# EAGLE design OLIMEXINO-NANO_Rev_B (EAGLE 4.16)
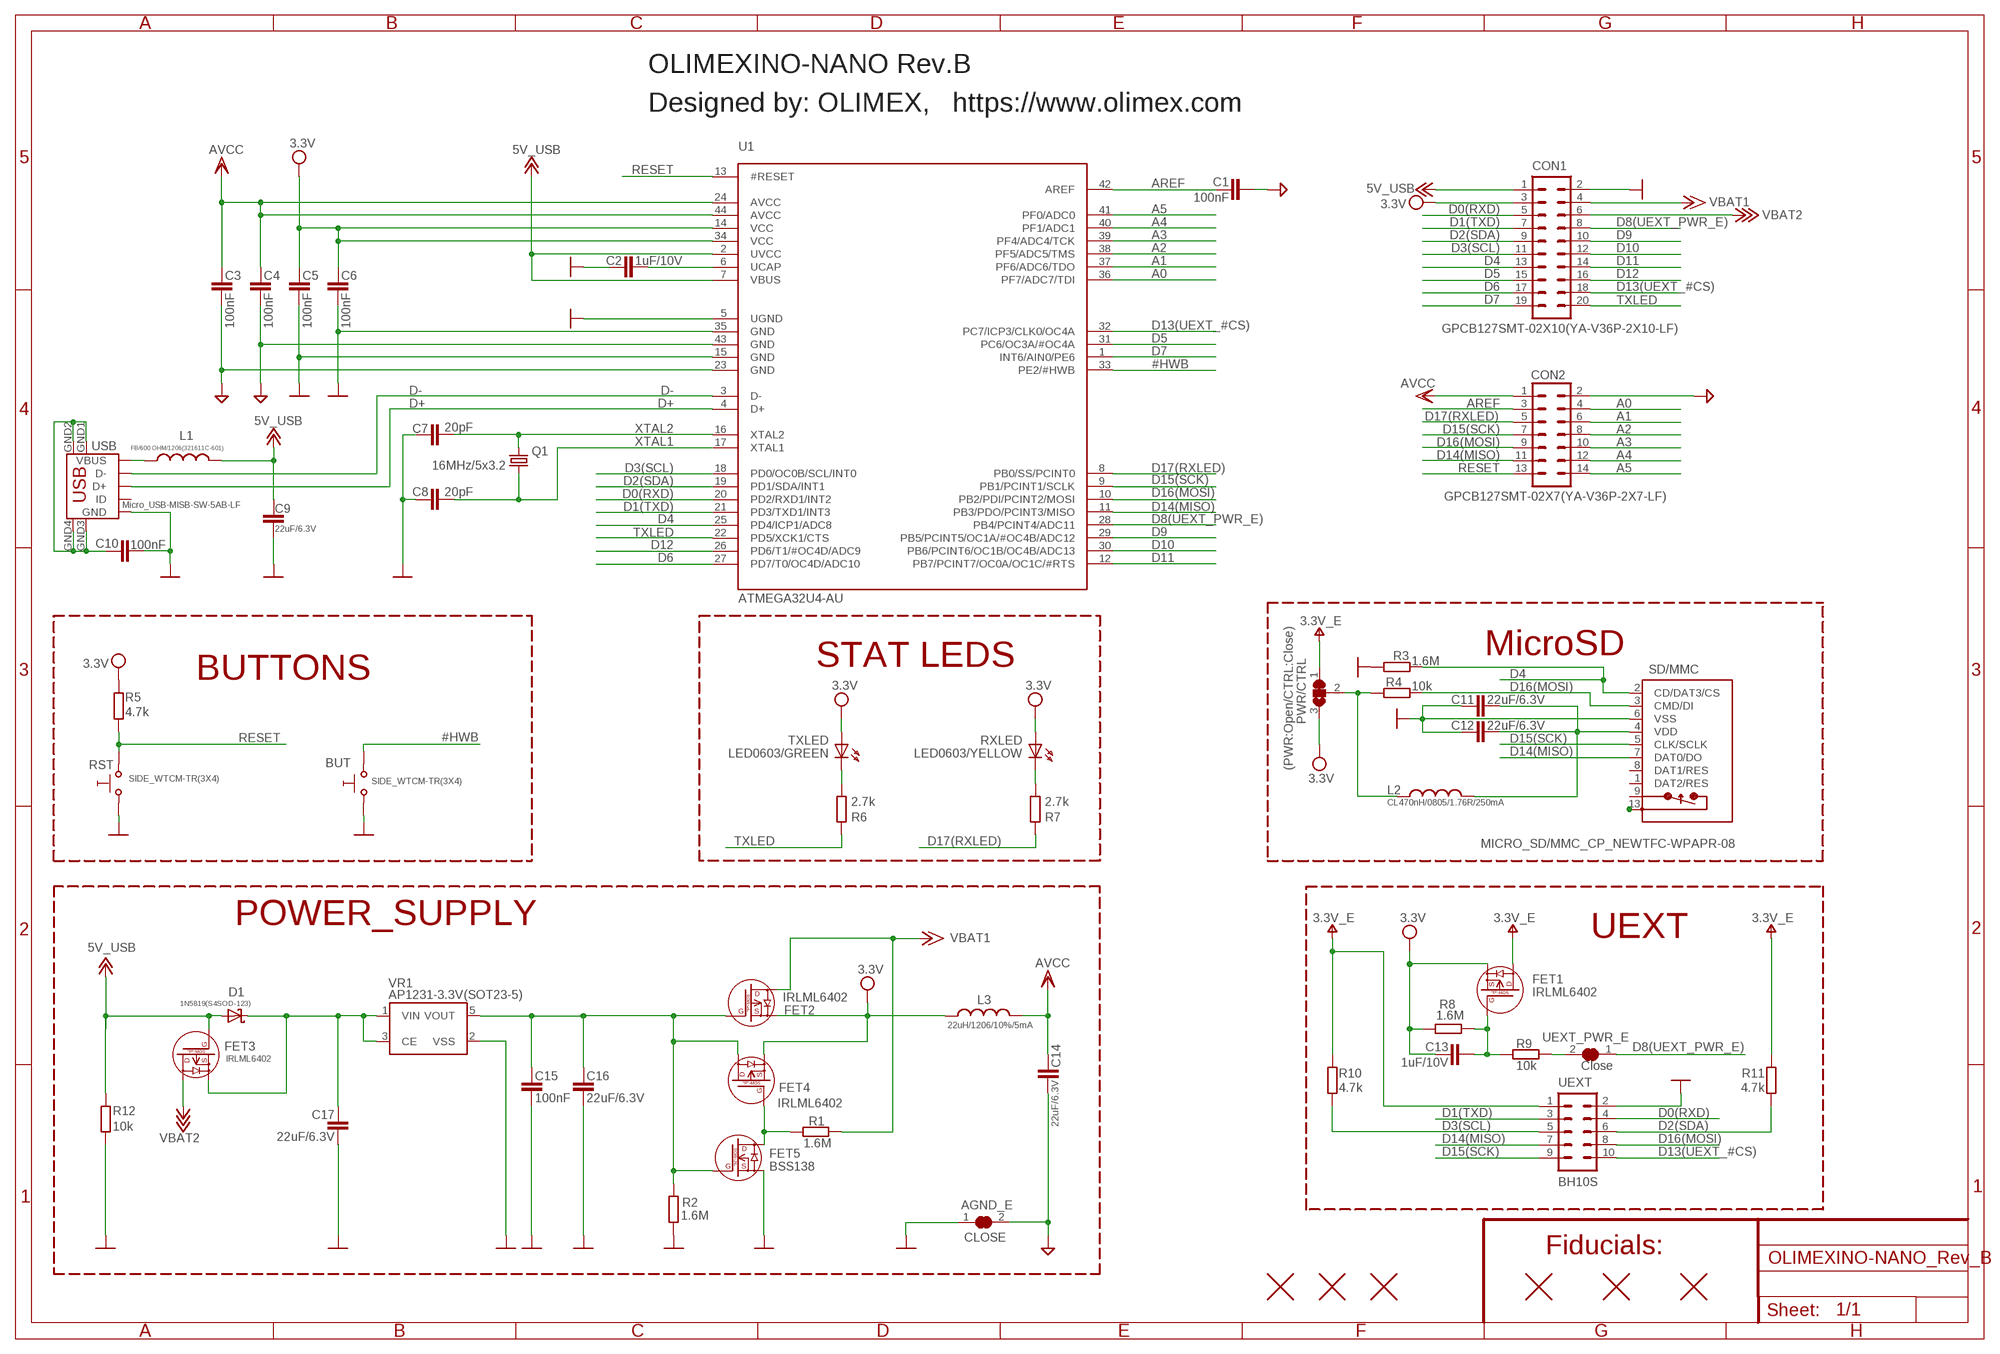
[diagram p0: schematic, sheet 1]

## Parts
AGND_E  CLOSE  SJSJ_1_SMALLER_CLOSE  [SJ_1_SMALLER_CLOSE]
BUT  SIDE_WTCM-TR(3X4)  SW-TAKTSIDE_WTCM-TR(3X4)  [SW_TAKT3X4]
C1  100nF  C-EUC0603_DWS  [C0603_DWS]
C2  1uF/10V  C-EUC0603_DWS  [C0603_DWS]
C3  100nF  C-EUC0402_TI  [C0402_TI]
C4  100nF  C-EUC0603_DWS  [C0603_DWS]
C5  100nF  C-EUC0603_DWS  [C0603_DWS]
C6  100nF  C-EUC0603_DWS  [C0603_DWS]
C7  20pF  C-EUC0603_DWS  [C0603_DWS]
C8  20pF  C-EUC0603_DWS  [C0603_DWS]
C9  22uF/6.3V  C-EUC0603_DWS  [C0603_DWS]
C10  100nF  C-EUC0603_DWS  [C0603_DWS]
C11  22uF/6.3V  C-EUC0603_DWS  [C0603_DWS]
C12  22uF/6.3V  C-EUC0603_DWS  [C0603_DWS]
C13  1uF/10V  C-EUC0603_DWS  [C0603_DWS]
C14  22uF/6.3V  C-EUC0603_DWS  [C0603_DWS]
C15  100nF  C-EUC0603_DWS  [C0603_DWS]
C16  22uF/6.3V  C-EUC0603_DWS  [C0603_DWS]
C17  22uF/6.3V  C-EUC0603_DWS  [C0603_DWS]
CON1  GPCB127SMT-02X10(YA-V36P-2X10-LF)  ML20YA-V36P-2X10-LF  [YA-V36P-2X10-LF]
CON2  GPCB127SMT-02X7(YA-V36P-2X7-LF)  ML14YA-V36P-2X7-LF  [YA-V36P-2X7-LF]
D1  1N5819(S4SOD-123)  SCHOTKKY7.62SS-1N5819(S4SOD-123)  [SOD-123]
FET1  IRLML6402  P-MOS+DIODIRLML6402  [SOT23]
FET2  IRLML6402  P-MOS+DIODIRLML6402  [SOT23]
FET3  IRLML6402  P-MOS+DIODIRLML6402  [SOT23]
FET4  IRLML6402  P-MOS+DIODIRLML6402  [SOT23]
FET5  BSS138  N-MOS+DIODBSS138(SOT23-3)  [SOT23]
FID1  FIDUCIAL  [FIDUCIAL-1X3]
FID2  FIDUCIAL  [FIDUCIAL-1X3]
FID3  FIDUCIAL  [FIDUCIAL-1X3]
FID4  FIDUCIAL  [FIDUCIAL-1X3]
FID5  FIDUCIAL  [FIDUCIAL-1X3]
FID6  FIDUCIAL  [FIDUCIAL-1X3]
L1  FB/600 OHM/1206(321611C-601)  L-USL3216C  [L3216C]
L2  CL470nH/0805/1.76R/250mA  L-USL0805_5MIL_DWS  [L0805_5MIL_DWS]
L3  22uH/1206/10%/5mA  L-USL3216C  [L3216C]
PWR/CTRL  (PWR:Open/CTRL:Close)  SJ2W6  [SJ_2_SMALL_12_TIED]
Q1  16MHz/5x3.2  HC49/S_E4SB25.000F20E15  [HCX-4S]
R1  1.6M  R-EU_R0603_5MIL_DWS  [R0603_5MIL_DWS]
R2  1.6M  R-EU_R0603_5MIL_DWS  [R0603_5MIL_DWS]
R3  1.6M  R-EU_R0603_5MIL_DWS  [R0603_5MIL_DWS]
R4  10k  R-EU_R0603_5MIL_DWS  [R0603_5MIL_DWS]
R5  4.7k  R-EU_R0603_5MIL_DWS  [R0603_5MIL_DWS]
R6  2.7k  R-EU_R0603_5MIL_DWS  [R0603_5MIL_DWS]
R7  2.7k  R-EU_R0603_5MIL_DWS  [R0603_5MIL_DWS]
R8  1.6M  R-EU_R0603_5MIL_DWS  [R0603_5MIL_DWS]
R9  10k  R-EU_R0603_5MIL_DWS  [R0603_5MIL_DWS]
R10  4.7k  R-EU_R0603_5MIL_DWS  [R0603_5MIL_DWS]
R11  4.7k  R-EU_R0603_5MIL_DWS  [R0603_5MIL_DWS]
R12  10k  R-EU_R0603_5MIL_DWS  [R0603_5MIL_DWS]
RST  SIDE_WTCM-TR(3X4)  SW-TAKTSIDE_WTCM-TR(3X4)  [SW_TAKT3X4]
RXLED  LED0603/YELLOW  LED0603DWS  [LED-0603]
SD/MMC  MICRO_SD/MMC_CP_NEWTFC-WPAPR-08  [TFC-WPAPR-08]
TXLED  LED0603/GREEN  LED0603DWS  [LED-0603]
U1  ATMEGA32U4-AU  ATMEGA32U4U  [TQFP44]
UEXT  BH10S  ML10SMD  [ML10_PADS]
UEXT_PWR_E  Close  SJSJ_1_SMALLER_CLOSE  [SJ_1_SMALLER_CLOSE]
USB  Micro_USB-MISB-SW-5AB-LF  MINI_USB9MISB-SW-5AB-LF  [MISB-SW-5AB-LF]
VR1  AP1231-3.3V(SOT23-5)  AP1231-33  [SOT-23-5]

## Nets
#HWB: BUT.1_1 U1.33(PE2/#HWB)
+12V: C9.1 CON1.1 D1.A FET3.1(G) L1.2 R12.1 U1.2(UVCC) U1.7(VBUS) ; supply symbol labelled 5V_USB
+15V: CON1.4 FET2.3(D) R1.1 ; supply symbol labelled VBAT1
+18V: CON1.6 FET3.3(D) ; supply symbol labelled VBAT2
A0: CON2.4 U1.36(PF7/ADC7/TDI)
A1: CON2.6 U1.37(PF6/ADC6/TDO)
A2: CON2.8 U1.38(PF5/ADC5/TMS)
A3: CON2.10 U1.39(PF4/ADC4/TCK)
A4: CON2.12 U1.40(PF1/ADC1)
A5: CON2.14 U1.41(PF0/ADC0)
AGND: AGND_E.2 C1.2 C3.2 C4.2 C14.2 CON2.2 U1.23(GND) U1.43(GND)
AREF: C1.1 CON2.3 U1.42(AREF)
D0(RXD): CON1.5 U1.20(PD2/RXD1/INT2) UEXT.4
D1(TXD): CON1.7 U1.21(PD3/TXD1/INT3) UEXT.3
D2(SDA): CON1.9 R11.1 U1.19(PD1/SDA/INT1) UEXT.6
D3(SCL): CON1.11 R10.1 U1.18(PD0/OC0B/SCL/INT0) UEXT.5
D4: CON1.13 R3.1 SD/MMC.2(CD/DAT3/CS) U1.25(PD4/ICP1/ADC8)
D5: CON1.15 U1.31(PC6/OC3A/#OC4A)
D6: CON1.17 U1.27(PD7/T0/OC4D/ADC10)
D7: CON1.19 U1.1(INT6/AIN0/PE6)
D8(UEXT_PWR_E): CON1.8 U1.28(PB4/PCINT4/ADC11) UEXT_PWR_E.1
D9: CON1.10 U1.29(PB5/PCINT5/OC1A/#OC4B/ADC12)
D10: CON1.12 U1.30(PB6/PCINT6/OC1B/OC4B/ADC13)
D11: CON1.14 U1.12(PB7/PCINT7/OC0A/OC1C/#RTS)
D12: CON1.16 U1.26(PD6/T1/#OC4D/ADC9)
D13(UEXT_#CS): CON1.18 U1.32(PC7/ICP3/CLK0/OC4A) UEXT.10
D14(MISO): CON2.11 SD/MMC.7(DAT0/DO) U1.11(PB3/PDO/PCINT3/MISO) UEXT.7
D15(SCK): CON2.7 SD/MMC.5(CLK/SCLK) U1.9(PB1/PCINT1/SCLK) UEXT.9
D16(MOSI): CON2.9 R4.1 SD/MMC.3(CMD/DI) U1.10(PB2/PDI/PCINT2/MOSI) UEXT.8
D17(RXLED): CON2.5 R7.2 U1.8(PB0/SS/PCINT0)
D+: U1.4(D+) USB.D+
D-: U1.3(D-) USB.D-
GND [pwr]: AGND_E.1 BUT.2_1 C2.1 C5.2 C6.2 C7.1 C8.1 C9.2 C10.2 C11.1 C12.1 C15.2 C16.2 C17.2 CON1.2 FET5.2(S) R2.2 R3.2 R12.2 RST.1_1 SD/MMC.6(VSS) U1.5(UGND) U1.15(GND) U1.35(GND) UEXT.2 USB.GND VR1.2(VSS)
N$2: FET4.1(G) FET5.3(D) R1.2
N$5: R6.1 TXLED.C
N$6: R9.2 UEXT_PWR_E.2
N$7: SD/MMC.10(PACK1) SD/MMC.11(PACK2) SD/MMC.12(PACK3) SD/MMC.13(PACK4)
N$8: C15.1 C16.1 FET2.1(G) FET4.3(D) FET5.1(G) R2.1 VR1.5(VOUT)
N$18: L2.1 PWR/CTRL.2 R4.2
N$19: C13.2 FET1.1(G) R8.2 R9.1
N$23: R7.1 RXLED.C
N$118: C10.1 USB.GND1 USB.GND2 USB.GND3 USB.GND4
RESET: CON2.13 R5.2 RST.2_1 U1.13(#RESET)
SD_VCC: C11.2 C12.2 L2.2 SD/MMC.4(VDD)
TXLED: CON1.20 R6.2 U1.22(PD5/XCK1/CTS)
UCAP: C2.2 U1.6(UCAP)
V+: FET1.3(D) PWR/CTRL.1 R10.2 R11.2 UEXT.1 ; supply symbol labelled 3.3V_E
VBUS: L1.1 USB.VBUS
VCC: C5.1 C6.1 C13.1 CON1.3 FET1.2(S) FET2.2(S) FET4.2(S) L3.1 PWR/CTRL.3 R5.1 R8.1 RXLED.A TXLED.A U1.14(VCC) U1.34(VCC) ; supply symbol labelled 3.3V
VDD: C3.1 C4.1 C14.1 CON2.1 L3.2 U1.24(AVCC) U1.44(AVCC) ; supply symbol labelled AVCC
VIN: C17.1 D1.C FET3.2(S) VR1.1(VIN) VR1.3(CE)
XTAL1: C8.2 Q1.2 U1.17(XTAL1)
XTAL2: C7.2 Q1.1 U1.16(XTAL2)
Unconnected: SD/MMC.1(DAT2/RES) SD/MMC.8(DAT1/RES) SD/MMC.9(CP_E) USB.ID

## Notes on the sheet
- OLIMEXINO-NANO Rev.B
- Designed by: OLIMEX,   https://www.olimex.com
- MicroSD
- STAT LEDS
- BUTTONS
- POWER_SUPPLY
- UEXT
- Fiducials:

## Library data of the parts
AGND_E UEXT_PWR_E = jumper:SJ: SMD solder JUMPER
BUT RST = gogo:SW-TAKT
C1-C17 = rcl:C-EU: CAPACITOR, European symbol
CON1 = con-harting-ml:ML20: HARTING
CON2 = con-harting-ml:ML14: HARTING
D1 = gogo:SCHOTKKY7.62SS
FET1-FET4 = Penko:P-MOS+DIOD
FET5 = Penko:N-MOS+DIOD
FID1-FID6 = SparkFunEagle-6-6-07:FIDUCIAL: Fiducial Alignment Points
L1-L3 = rcl:L-US: INDUCTOR, American symbol
PWR/CTRL = jumper:SJ2W: SMD solder JUMPER
Q1 = crystal:HC49/S: CRYSTAL
R1-R12 = rcl:R-EU_: RESISTOR, European symbol
RXLED TXLED = DOUBLE-SIDE:LED
SD/MMC = OLIMEX_CONNECTORS:MICRO_SD/MMC_CP_NEW
U1 = OLIMEX_IC:ATMEGA32U4: 8-bit Microcontroller with 16/32K Bytes of ISP Flash and USB Controller
UEXT = con-harting-ml:ML10: HARTING
USB = OLIMEX_CONNECTORS:MINI_USB9
VR1 = OLIMEX_DISCRET:AP1231

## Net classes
1 pwr: width 0.25 mm

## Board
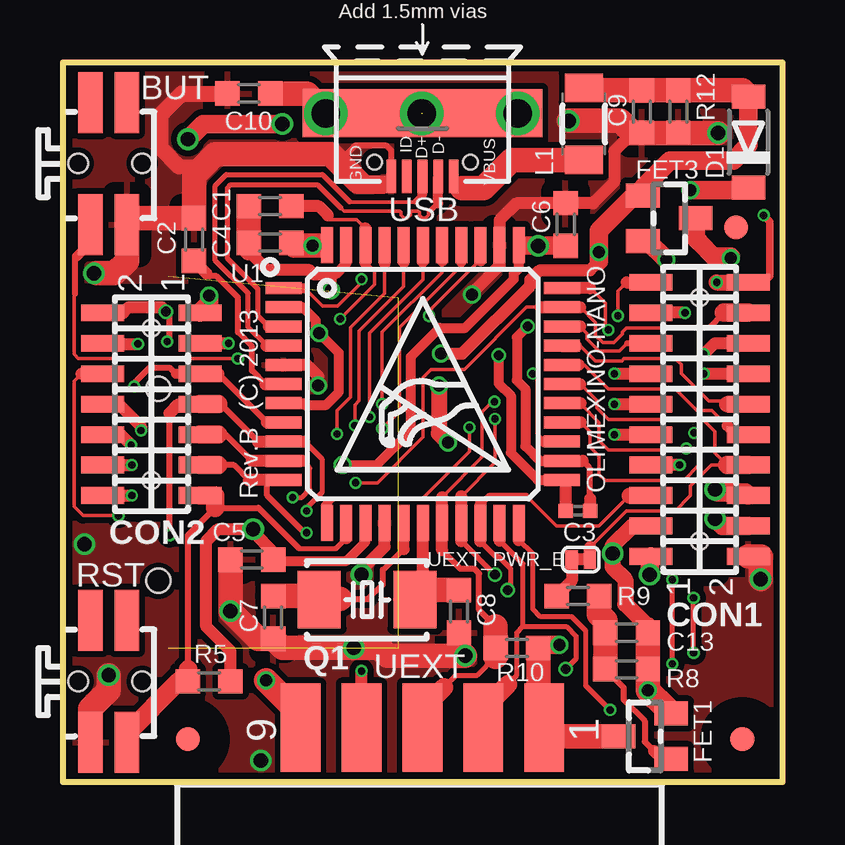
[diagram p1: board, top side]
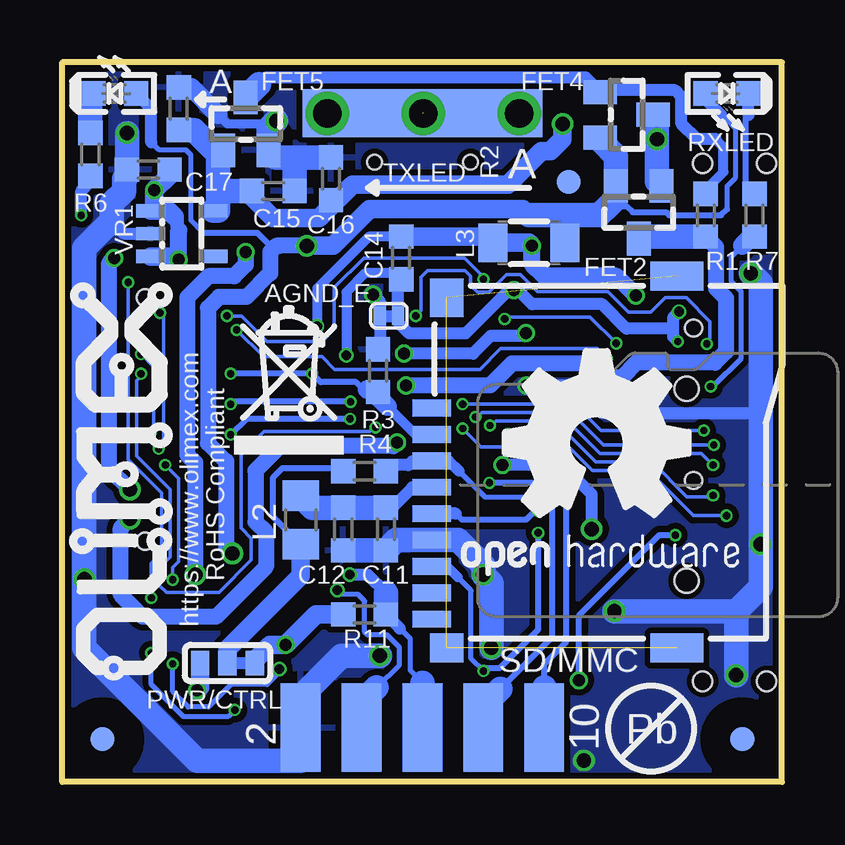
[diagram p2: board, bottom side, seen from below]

Size 30 x 30 mm. Coordinates in mm from the lower left corner, seen from the top.
Outline: 0,0 30,0 30,30 0,30 0,0
Copper layers (1+16): Top 0.035mm / dielectric 1.5mm / Bottom 0.035mm
Design rules "default": minimum track width 6mil, minimum drill 0.4mm, track to track 0.2mm, track to pad 0.2mm, pad to pad 0.2mm, via to via 0.2mm, smd to smd 1mil, copper to edge 10mil, drill to drill 8mil, minimum pad ring 8mil, minimum via ring 4mil, stop-mask expansion 4mil, vias tented up to drill 25mil, thermal gap 20mil
tRestrict: 4 lines

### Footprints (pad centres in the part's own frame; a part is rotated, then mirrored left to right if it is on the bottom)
SJ_1_SMALLER_CLOSE = smd 0.508 x 0.762: 1 -0.381,0; 2 0.381,0
SW_TAKT3X4 = smd 2.54 x 1.016: 1_1 -2.54,0.762; 1_2 2.54,0.762; 2_1 -2.54,-0.762; 2_2 2.54,-0.762 | hole 0.8: 0,-1.397; 0,1.27
C0603_DWS = smd 1.016 x 1.016: 1 -0.889,0; 2 0.889,0
C0402_TI = smd 0.61 x 0.584: 1 -0.508,0; 2 0.508,0
YA-V36P-2X10-LF = smd 0.7 x 1.8: 1 -5.715,2.032; 2 -5.715,-2.032; 3 -4.445,2.032; 4 -4.445,-2.032; 5 -3.175,2.032; 6 -3.175,-2.032; 7 -1.905,2.032; 8 -1.905,-2.032; 9 -0.635,2.032; 10 -0.635,-2.032; 11 0.635,2.032; 12 0.635,-2.032; 13 1.905,2.032; 14 1.905,-2.032; 15 3.175,2.032; 16 3.175,-2.032; 17 4.445,2.032; 18 4.445,-2.032; 19 5.715,2.032; 20 5.715,-2.032 | hole 0.7: -5.08,0; 5.08,0
YA-V36P-2X7-LF = smd 0.7 x 1.8: 1 -3.81,2.032; 2 -3.81,-2.032; 3 -2.54,2.032; 4 -2.54,-2.032; 5 -1.27,2.032; 6 -1.27,-2.032; 7 0,2.032; 8 0,-2.032; 9 1.27,2.032; 10 1.27,-2.032; 11 2.54,2.032; 12 2.54,-2.032; 13 3.81,2.032; 14 3.81,-2.032 | hole 0.7: -3.175,0; 3.175,0
SOD-123 = smd 1 x 1.4: A 1.9,0; C -1.9,0
SOT23 = smd 1 x 1.4: 1 -0.95,-1.1; 2 0.95,-1.1; 3 0,1.1
FIDUCIAL-1X3 = smd 1 x 1: 1 0,0
L3216C = smd 1.2 x 1.6: 1 -1.5,0; 2 1.5,0
L0805_5MIL_DWS = smd 1.27 x 1.524: 1 -1.016,0; 2 1.016,0
SJ_2_SMALL_12_TIED = smd 0.762 x 1.016: 1 -1.143,0; 2 0,0; 3 1.143,0
HCX-4S = smd 1.8 x 2.4: 1 -2,0; 2 2,0
R0603_5MIL_DWS = smd 1.016 x 1.016: 1 -0.889,0; 2 0.889,0
LED-0603 = smd 1.016 x 1.016: A 0.889,0; C -0.889,0
TFC-WPAPR-08 = smd 0.7 x 1.6: 1 -3.2,-0.125; 2 -2.1,-0.125; 3 -1,-0.125; 4 0.1,-0.125; 5 1.2,-0.125; 6 2.3,-0.125; 7 3.4,-0.125; 8 4.5,-0.125; 9 5.6,-0.125 | smd 1.2 x 1.4: 10 6.8,0.5 | smd 1.6 x 1.4: 11 -7.8,0.5 | smd 1.2 x 2.2: 12 6.8,10.1; 13 -8.7,10.1 | hole 1: 4,10.5; -4,10.5
TQFP44 = smd 1.5 x 0.5: 1 -5.78,3.95; 2 -5.78,3.15; 3 -5.78,2.35; 4 -5.78,1.55; 5 -5.78,0.75; 6 -5.78,-0.05; 7 -5.78,-0.85; 8 -5.78,-1.65; 9 -5.78,-2.45; 10 -5.78,-3.25; 11 -5.78,-4.05; 23 5.82,-4.05; 24 5.82,-3.25; 25 5.82,-2.45; 26 5.82,-1.65; 27 5.82,-0.85; 28 5.82,-0.05; 29 5.82,0.75; 30 5.82,1.55; 31 5.82,2.35; 32 5.82,3.15; 33 5.82,3.95 | smd 0.5 x 1.5: 12 -3.98,-5.85; 13 -3.18,-5.85; 14 -2.38,-5.85; 15 -1.58,-5.85; 16 -0.78,-5.85; 17 0.02,-5.85; 18 0.82,-5.85; 19 1.62,-5.85; 20 2.42,-5.85; 21 3.22,-5.85; 22 4.02,-5.85; 34 4.02,5.75; 35 3.22,5.75; 36 2.42,5.75; 37 1.62,5.75; 38 0.82,5.75; 39 0.02,5.75; 40 -0.78,5.75; 41 -1.58,5.75; 42 -2.38,5.75; 43 -3.18,5.75; 44 -3.98,5.75
ML10_PADS = smd 1.651 x 3.683: 1 -5.08,-0.229; 3 -2.54,-0.229; 5 0,-0.229; 7 2.54,-0.229; 9 5.08,-0.229 | smd 1.651 x 3.683 bottom: 2 -5.08,-0.229; 4 -2.54,-0.229; 6 0,-0.229; 8 2.54,-0.229; 10 5.08,-0.229
MISB-SW-5AB-LF = drill 1.2 round: 1 1.47,3.97; 2 1.47,-0.03; 3 1.47,-4.03 | smd 1.4 x 0.4: D+ 4.1,0; D- 4.1,0.65; GND 4.1,-1.3; ID 4.1,-0.65; VBUS 4.1,1.3 | smd 2 x 2: GND1 1.45,4; GND2 1.45,-4 | smd 2 x 6.4: GND3 1.45,-0.05 | smd 2 x 10 bottom: GND4 1.45,0 | hole 0.6: 3.5,-2; 3.5,2
SOT-23-5 = smd 0.55 x 1.2: 1 -0.95,-1.3; 2 0,-1.3; 3 0.95,-1.3; 4 0.95,1.3; 5 -0.95,1.3

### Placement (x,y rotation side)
AGND_E  16.38,19.43 0 bottom
BUT  1.91,25.78 90 top
C1  8.64,24 180 top
C2  5.46,22.61 270 top
C3  21.46,11.3 180 top
C4  8.64,22.48 180 top
C5  7.87,9.27 180 top
C6  20.95,23.24 90 top
C7  8.76,6.86 90 top
C8  16.51,7.11 90 top
C9  24.13,27.94 270 top
C10  7.75,28.7 180 top
C11  16.51,10.54 90 bottom
C12  18.29,10.54 90 bottom
C13  23.5,6.22 180 top
C14  15.88,21.84 270 bottom
C15  21.21,24.64 0 bottom
C16  18.8,25.15 90 bottom
C17  26.42,25.53 180 bottom
CON1  26.54,15.11 90 top
CON2  3.68,15.75 270 top
D1  28.57,26.67 90 top
FET1  24.26,1.91 90 top
FET2  5.97,23.75 180 bottom
FET3  25.27,23.5 270 top
FET4  6.48,27.81 270 bottom
FET5  22.35,27.43 0 bottom
FID1  28.32,1.78 0 top
FID2  5.21,1.78 0 top
FID3  28.07,23.11 0 top
FID4  28.32,1.78 180 bottom
FID5  1.65,1.78 90 bottom
FID6  8.89,25.02 0 bottom
L1  21.72,27.43 90 top
L2  20.07,10.92 90 bottom
L3  10.54,22.48 180 bottom
PWR/CTRL  23.11,4.95 180 bottom
Q1  12.67,7.59 0 top
R1  3.17,23.62 90 bottom
R2  25.15,28.07 90 bottom
R3  16.84,17.14 90 bottom
R4  17.4,12.95 180 bottom
R5  6.1,4.19 180 top
R6  28.83,26.16 270 bottom
R7  1.14,23.62 270 bottom
R8  23.5,4.7 180 top
R9  21.46,7.75 180 top
R10  18.92,5.59 0 top
R11  17.4,6.99 180 bottom
R12  25.65,27.94 270 top
RST  1.91,4.19 90 top
RXLED  2.29,28.7 180 bottom
SD/MMC  14.48,12.38 270 bottom
TXLED  27.81,28.7 0 bottom
U1  14.99,16.64 0 top
U$1  [RECYCLE_BIN1/8]  22.85,13.65 0 bottom
U$2  [PB_SMALL]  5.45,2.22 0 bottom
U$3  [LOGO-OPENHARDWARE_8X8]  7.73,14.04 0 bottom
U$11  [ESD_SYMBOL]  11.44,13.02 0 top
U$12  [OLIMEX1_V]  25.27,21.97 90 bottom
UEXT  14.99,2.03 180 top
UEXT_PWR_E  21.59,9.27 180 top
USB  14.99,29.34 270 top
VR1  25.02,22.86 270 bottom

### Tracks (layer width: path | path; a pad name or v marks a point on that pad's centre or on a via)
#HWB  (via drill 0.3)
  Top 0.152: 21.98,20.59 22.61,19.96 22.61,18.97 v22.73,18.85 | 1.14,22.48 BUT.1_1 | 0.51,20.34 0.46,20.3 0.46,17.83 0.64,17.65 3.12,17.65 3.15,17.68 4.62,17.68 4.65,17.65 v7.29,17.65
  Top 0.254: 0.51,20.34 0.51,21.84 0.58,21.92
  Top 0.406: 0.58,21.92 1.14,22.48
  Top 0.508: 21.98,20.59 U1.33
  Bottom 0.152: v7.29,17.65 7.7,18.06 11.73,18.06 12.6,17.2 18.64,17.2 19.18,17.73 21.61,17.73 v22.73,18.85
+12V  (via drill 0.5, 0.6)
  Top 0.406: U1.2 9.98,19.79 10.54,19.23 10.54,18.92 10.67,18.8 v10.67,18.72 11.51,17.88 11.51,16.26 10.97,15.72 10.06,15.72 9.99,15.79 U1.7
  Top 0.508: v15.75,17.86 16.64,17.86 19.48,20.7 19.48,20.93 19.89,21.34 21.97,21.34 22.35,21.72
  Top 0.762: D1.A 28.57,26.54 27.94,25.91 25.3,25.91 24.17,24.78 FET3.1 23.81,24.45 22.35,22.99 v22.35,22.1 22.35,21.72 | v24.46,8.64 24.46,9.35 CON1.1
  Top 1.016: D1.A 28.32,28.83 R12.1 C9.1 21.82,28.83 L1.2
  Bottom 0.508: v10.67,18.72 10.79,18.59 12.14,18.59 12.88,17.86 v15.75,17.86
  Bottom 0.66: v24.46,8.64 24.46,13.31 24.79,13.64 24.79,20.19 23.9,21.08 22.84,21.08 22.35,21.57 v22.35,22.1
+15V  (via drill 0.5, 0.6)
  Top 0.66: v15.67,16.54 15.67,14.53 v16.05,14.15
  Top 0.762: CON1.4 27.48,10.67 v27.18,10.97
  Bottom 0.66: v27.18,10.97 27.56,10.59 27.56,7.8 26.64,6.88 23.6,6.88 21.51,8.97 21.51,10.41 21.95,10.85 21.95,12.98 20.93,13.99 16.2,13.99 v16.05,14.15 | v15.67,16.54 12.17,16.54 11.25,17.45 8.28,17.45 7.7,16.87 6.68,16.87 6.07,17.48 2.79,17.48 2.34,17.93 2.34,20.17 2.74,20.57 2.74,22.3 R1.1
  Bottom 1.016: FET2.3 5.88,22.73 R1.1
+18V  (via drill 0.5, 0.6)
  Top 0.762: FET3.3 26.37,22.65 26.54,22.48 27.12,21.9 27.84,21.9 v27.84,21.84 | CON1.6 28.45,12.06 27.3,12.06 v27.18,12.19
  Bottom 0.66: v27.84,21.84 28.04,21.64 28.04,13.06 v27.18,12.19
A0  (via drill 0.3)
  Top 0.152: v15.27,19.43 15.37,19.53 15.37,19.74 17.38,21.75 17.41,21.75
  Top 0.508: CON2.4 1.68,18.26 v3.12,18.26 | 17.41,21.75 U1.36
  Bottom 0.152: v3.12,18.26 3.12,18.36 3,18.49 3,19.2 3.99,20.19 4.85,20.19 5.46,19.58 6.4,19.58 7.26,20.45 10.19,20.45 10.9,21.16 11.48,21.16 12.22,20.42 12.7,20.42 12.98,20.7 12.98,21.08 13.21,21.31 14.78,21.31 15.04,21.06 15.04,19.66 v15.27,19.43
A1  (via drill 0.3)
  Top 0.152: 0.76,17.02 0.46,16.71 0.46,11.48 0.84,11.1 v2.31,11.1 | 16.61,21.66 16.61,21.53 14.02,18.95 14.02,15.44 v13.31,14.73
  Top 0.406: 16.61,21.66 U1.37
  Top 0.508: 0.76,17.02 CON2.6
  Bottom 0.152: v13.31,14.73 12.55,13.97 8.89,13.97 7.9,12.98 5.56,12.98 3.68,11.1 v2.31,11.1
A2  (via drill 0.3)
  Top 0.152: 15.81,21.75 15.81,21.24 13.31,18.75 v13.31,15.75
  Top 0.508: 15.81,21.75 U1.38 | CON2.8 2.31,15.75 3.25,14.81 v3.25,14.66
  Bottom 0.152: v13.31,15.75 8.64,15.75 7.54,14.66 v3.25,14.66
A3  (via drill 0.3)
  Top 0.152: 15.01,21.71 15.01,20.95 12.78,18.72 v12.78,15.21
  Top 0.508: 15.01,21.71 U1.39 | CON2.10 2.41,14.48 v2.85,14.05
  Bottom 0.152: v12.78,15.21 12.68,15.21 12.5,15.39 8.79,15.39 7.44,14.05 v2.85,14.05
A4  (via drill 0.3)
  Top 0.152: 14.21,21.67 14.21,20.66 12.34,18.8 12.34,15.9 12.17,15.72 v12.17,14.86
  Top 0.508: 14.21,21.67 U1.40 | CON2.12 v2.87,13.21
  Bottom 0.152: v12.17,14.86 12.09,14.86 11.91,15.04 8.94,15.04 7.59,13.69 3.35,13.69 v2.87,13.21
A5  (via drill 0.3)
  Top 0.152: v11.43,14.5 11.43,15.49 11.99,16.05 11.99,18.95 13.41,20.37 13.41,21.65
  Top 0.508: 13.41,21.65 U1.41 | CON2.14 v2.87,11.94
  Bottom 0.152: v11.43,14.5 8.91,14.5 7.75,13.34 5.41,13.34 3.96,11.89 2.92,11.89 v2.87,11.94
AGND  (via drill 0.3, 0.4, 0.5)
  Top 0.254: v4.29,19.61 4.42,19.48 4.42,18.44 v4.34,18.36
  Top 0.406: U1.43 11.81,21.61 11.35,21.16 11.18,21.16 | U1.23 19.8,12.59 18.67,13.72 18.67,16.1 18.16,16.61 v18.16,17.78
  Top 0.508: 7.75,22.12 8.53,21.34 10.29,21.34 10.46,21.16 11.18,21.16 v11.18,20.5 | CON2.2 2.52,19.56 2.74,19.79 4.12,19.79 v4.29,19.61 | U1.23 20.95,12.44 C3.2
  Top 0.762: 7.75,22.12 C4.2
  Top 1.016: C4.2 C1.2
  Bottom 0.406: C14.2 16.13,21.21 17.37,21.21 18.16,20.42 v18.16,17.78
  Bottom 0.508: v4.29,19.61 4.55,19.36 4.55,18.9 | 4.55,18.9 6.48,18.9 7.49,19.91 10.41,19.91 11,20.5 v11.18,20.5 11.38,20.5 13.18,18.69 15.54,18.69 16,19.15 AGND_E.2 16,20.83 C14.2 | 4.55,18.9 4.55,18.57 v4.34,18.36
AREF  (via drill 0.3)
  Top 0.152: 12.61,23.08 12.24,23.44 11.1,23.44 11.05,23.5 11.05,23.62 | 12.61,21.67 12.98,21.29 12.98,20.73 v11.56,19.3
  Top 0.508: CON2.3 v6.91,18.29 | 12.61,23.08 U1.42 12.61,21.67 | 11.05,23.62 10.67,24 C1.1
  Bottom 0.152: v6.91,18.29 8,19.38 11.48,19.38 v11.56,19.3
D0(RXD)  (via drill 0.4)
  Top 0.152: 23.62,11.94 22.35,10.67 20.57,10.67 19.3,11.94
  Top 0.203: 17.4,10.03 18.03,9.4 18.16,9.4 18.67,8.89 18.67,8.13 v18.54,8
  Top 0.254: 17.41,11.56 17.78,11.94 19.3,11.94
  Top 0.508: 17.4,10.03 U1.20 17.41,11.56
  Top 0.66: 23.62,11.94 CON1.5
  Bottom 0.203: v18.54,8 18.36,7.82 17.68,7.82 17.4,7.54 17.4,6.25 17.27,6.12 16.46,6.12 15.95,5.61 15.95,4.88 16.89,3.94
  Bottom 1.016: UEXT.4 17.53,3.3 16.89,3.94
D1(TXD)  (via drill 0.3, 0.4)
  Top 0.203: 18.54,4.06 18.92,4.45 18.92,6.22 19.18,6.48 | 19.18,6.48 19.18,9.09 18.21,10.06 | 19.18,6.48 20.98,6.48 21.39,6.07 21.39,5.13 v20.95,4.7 | v25.4,4.93 v25.4,8.43
  Top 0.508: 18.21,10.06 U1.21 | v25.7,13.21 CON1.7
  Top 0.762: UEXT.3 17.53,3.05 18.54,4.06
  Bottom 0.152: v25.7,13.21 25.15,12.65 25.15,9.2 25.4,8.94 v25.4,8.43
  Bottom 0.203: v25.4,4.93 25.4,3.76 24.77,3.12 23.9,3.12 22.96,4.06 21.46,4.06 20.95,4.57 v20.95,4.7
D2(SDA)  (via drill 0.3, 0.4)
  Top 0.152: 16.61,11.91 18.01,13.31 v18.01,15.14
  Top 0.203: v18.01,8.64 16.61,10.04
  Top 0.508: v22.99,14.48 CON1.9 | 16.61,10.04 U1.19 16.61,11.91
  Bottom 0.203: 14.99,4.14 15.49,4.65 15.49,5.97 15.93,6.4
  Bottom 0.254: v18.01,15.14 22.33,15.14 v22.99,14.48
  Bottom 0.508: 15.93,6.4 R11.1 | 16.51,7.87 17.27,8.64 v18.01,8.64
  Bottom 1.016: UEXT.6 14.99,4.14 | R11.1 16.51,7.87
D3(SCL)  (via drill 0.3)
  Top 0.152: 15.81,11.87 17.48,13.54 17.48,15.42 17.91,15.85 v17.98,15.85
  Top 0.203: 15.88,3.94 16.38,4.45 17.27,4.45 18.03,5.21
  Top 0.254: 18.03,6.48 17.35,7.16 17.35,8.69 17.14,8.89 16.57,8.89 15.81,9.65
  Top 0.508: v22.99,15.75 CON1.11 | 15.81,9.65 U1.18 15.81,11.87
  Top 0.762: UEXT.5 14.99,3.05 15.88,3.94
  Top 1.016: 18.03,5.21 R10.1 18.03,6.48
  Bottom 0.254: v17.98,15.85 22.89,15.85 v22.99,15.75
D4  (via drill 0.3)
  Top 0.152: 20.1,14.19 19.76,14.53 19.76,16.84 v19.58,17.02
  Top 0.508: 20.1,14.19 U1.25 | v22.99,17.02 CON1.13
  Bottom 0.254: v22.99,17.02 v19.58,17.02 19.23,16.66 17.75,16.66 17.45,16.36 17.3,16.36
  Bottom 0.406: SD/MMC.2 15.27,14.48 16.43,15.65
  Bottom 0.762: 17.3,16.36 16.94,16.36 R3.1 16.84,16.05 16.43,15.65
D5
  Top 0.152: 21.55,18.99 21.84,18.69 21.84,18.47 22.35,17.96 23.19,17.96 23.52,18.29
  Top 0.254: 23.52,18.29 CON1.15
  Top 0.508: U1.31 21.55,18.99
D6  (via drill 0.3)
  Top 0.152: v25.98,13.89 25.93,13.84 22.73,13.84 22.35,14.22 22.35,14.99 21.59,15.75 21.59,15.79
  Top 0.508: v25.93,19.56 CON1.17 | 21.59,15.79 U1.27
  Bottom 0.152: v25.98,13.89 25.78,14.1 25.78,19.33 25.93,19.48 v25.93,19.56
D7  (via drill 0.3)
  Top 0.152: 10.07,20.59 10.82,19.84 11.46,19.84 12.45,20.83 v12.45,20.95 | 23.5,20.83 23.14,20.47 v23.14,19.43
  Top 0.406: U1.1 10.07,20.59
  Top 0.508: 23.5,20.83 CON1.19
  Bottom 0.152: v12.45,20.95 12.45,21.06 13.23,21.84 17.42,21.84 18.67,20.6 18.67,18.87 19.18,18.36 21.46,18.36 22.53,19.43 v23.14,19.43
D8(UEXT_PWR_E)
  Top 0.152: 21.56,16.59 22.25,15.9 22.25,15.6 22.73,15.11 26.67,15.11 27.18,14.61 27.18,13.72 27.69,13.21 27.03,13.21 26.16,12.34 26.16,11.94 25.53,11.3 23.5,11.3 21.97,9.78
  Top 0.508: 21.56,16.59 U1.28 | UEXT_PWR_E.1 21.97,9.78
  Top 0.762: 27.69,13.21 CON1.8
D9
  Top 0.152: 27.69,14.86 27.05,15.49 26.42,15.49 25.53,16.38 22.73,16.38 21.73,17.39 21.5,17.39
  Top 0.457: 27.69,14.86 28.07,14.48 CON1.10
  Top 0.508: U1.29 21.5,17.39
D10
  Top 0.152: 27.69,15.75 27.56,15.88 26.92,15.88 25.78,17.02 25.78,17.4 25.53,17.65 23.39,17.65 23.29,17.55 22.2,17.55 21.59,18.16 21.39,18.16
  Top 0.457: 20.83,18.16 U1.30
  Top 0.508: 21.39,18.16 20.83,18.16
  Top 0.66: 27.69,15.75 CON1.12
D11  (via drill 0.3)
  Top 0.152: 11.01,11.49 11.35,11.84 15.01,11.84 16.94,13.77 v16.94,14.78
  Top 0.508: v26.72,17.02 CON1.14 | U1.12 11.01,11.49
  Bottom 0.152: v26.72,17.02 26.72,16.92 26.9,16.74 26.9,13.59 25.5,12.19 25.5,9.37 25.93,8.94 25.93,8.18 25.65,7.9 23.47,7.9 22.12,9.25 22.12,10.16 22.55,10.59 22.55,13.64 21.59,14.61 17.2,14.61 17.02,14.78 v16.94,14.78
D12  (via drill 0.3)
  Top 0.152: 21.59,14.99 21.97,14.61 21.97,13.97 22.35,13.59 22.35,12.83 22.61,12.57 25.88,12.57 26.52,13.21 26.52,14.35 v26.31,14.55
  Top 0.508: 21.59,14.99 U1.26 | CON1.16 27.18,18.29 v26.72,17.83
  Bottom 0.152: v26.31,14.55 26.19,14.68 26.19,17.3 v26.72,17.83
D13(UEXT_#CS)  (via drill 0.3)
  Top 0.152: 26.92,18.92 23.5,18.92 23.32,18.75 23.32,18.67 22.96,18.31 22.5,18.31 22.2,18.62 22.2,19.15 21.57,19.79 | v12.19,12.47 13.11,12.47 15.01,14.38 15.01,16.87 15.34,17.2 16.74,17.2 19.33,19.79 19.91,19.79
  Top 0.254: 26.92,18.92 27.56,19.56
  Top 0.508: 21.57,19.79 U1.32 19.91,19.79
  Top 0.762: 27.56,19.56 CON1.18
  Bottom 0.254: 9.91,3.94 9.91,4.93 8.99,5.84 8.99,12.12 9.35,12.47 v12.19,12.47
  Bottom 1.016: UEXT.10 9.91,3.94
D14(MISO)  (via drill 0.3)
  Top 0.254: 7.75,12.59 7.13,13.21 6.48,13.21 | v10.16,10.39 10.13,10.41 10.03,10.41 8.51,11.94 8.51,12.59
  Top 0.508: 7.75,12.59 8.51,12.59 U1.11 | UEXT.7 v12.45,4.62
  Top 0.762: 6.48,13.21 CON2.11
  Bottom 0.203: 13.51,8.53 12.95,7.98 12.95,5.13 v12.45,4.62
  Bottom 0.254: v12.45,4.62 12.32,4.75 11.76,4.75 10.16,6.35 v10.16,10.39
  Bottom 0.406: SD/MMC.7 13.96,8.98 13.51,8.53
D15(SCK)  (via drill 0.3, 0.5)
  Top 0.203: 10.07,14.19 10.79,13.46 10.79,12.06 10.16,11.43 v10.16,11.3
  Top 0.254: 8.13,14.19 6.57,15.75 6.48,15.75 | v4.45,10.29 4.45,15.37
  Top 0.508: 8.13,14.19 U1.9 10.07,14.19 | CON2.7 4.83,15.75 4.45,15.37
  Top 0.762: CON2.7 6.48,15.75
  Top 1.016: UEXT.9 9.91,2.79 v8.46,4.24
  Bottom 0.254: v8.46,4.24 8.46,6.93 5.11,10.29 v4.45,10.29 | v10.16,11.3 10.29,11.3 10.67,10.92 13.34,10.92 13.6,11.18
  Bottom 0.508: 13.6,11.18 SD/MMC.5
D16(MOSI)  (via drill 0.3)
  Top 0.203: 9.98,13.39 10.29,13.08 10.29,12.19 9.96,11.86 v9.58,11.86
  Top 0.254: 7.87,13.39 6.78,14.48 6.48,14.48
  Top 0.508: 7.87,13.39 U1.10 9.98,13.39
  Top 0.762: 6.48,14.48 CON2.9
  Bottom 0.203: 13.46,12.95 12.37,11.86 v9.58,11.86
  Bottom 0.254: 11.73,3.89 9.58,6.04 v9.58,11.86
  Bottom 0.457: SD/MMC.3 13.89,13.38 13.46,12.95
  Bottom 0.508: SD/MMC.3 14.63,13.36 15.42,13.36 15.57,13.21 16.26,13.21 R4.1
  Bottom 0.762: UEXT.8 12.45,3.17
  Bottom 1.016: 12.45,3.17 11.73,3.89
D17(RXLED)  (via drill 0.3)
  Top 0.254: 6.48,17.02 8.51,14.99 | v2.97,16.48 2.97,16.64 3.61,17.27 4.45,17.27 4.7,17.02
  Top 0.406: 4.7,17.02 CON2.5
  Top 0.508: CON2.5 6.48,17.02 | 8.51,14.99 U1.8
  Bottom 0.203: v2.97,16.48 2.87,16.48 1.7,17.65 1.7,20.45 2.11,20.85 2.11,21.89 1.65,22.35
  Bottom 0.762: 1.65,22.35 1.27,22.73 R7.2
D+
  Top 0.152: 11.96,24.18 14.66,24.18
  Top 0.203: 14.66,24.18 14.99,24.51 | 11.96,24.18 10.82,25.32 6.81,25.32 6.35,24.87 6.35,21.74 7.72,20.37 7.72,18.95 8.48,18.19
  Top 0.406: 14.99,24.51 USB.D+
  Top 0.508: U1.4 8.48,18.19
D-
  Top 0.152: 11.58,23.93 11.71,23.8 14.05,23.8 14.1,23.75 14.1,23.62 14.22,23.5 14.35,23.5 14.48,23.62 14.48,23.75 14.53,23.8 14.81,23.8 14.86,23.75 14.86,23.62 14.99,23.5 15.11,23.5 15.24,23.62 15.24,23.75 15.29,23.8 15.31,23.8
  Top 0.203: 8.57,18.99 8.13,19.43 8.13,20.55 6.86,21.82 6.86,24.77 6.99,24.89 10.62,24.89 11.58,23.93 | 15.31,23.8 15.64,24.13
  Top 0.406: 15.64,24.13 USB.D-
  Top 0.508: U1.3 8.57,18.99
GND  (via drill 0.5, 0.6)
  Top 0.254: 11.18,26.16 11.81,26.16 12.19,26.54 13.43,26.54 | USB.GND 13.69,26.32 13.46,26.54
  Top 0.381: USB.GND 13.69,24.89 13.34,24.89
  Top 0.508: v10.64,16.52 10.64,16.92 10.17,17.39 U1.5 | U1.15 13.41,9.8 12.45,8.84 v12.45,8.64 | CON1.2 28.07,9.4 | v17.04,20.32 17.02,20.34 18.21,21.53 U1.35 18.21,23.41 18.92,24.13 C6.2 22.1,24.13 22.99,25.02 22.99,26.29 23.75,27.05
  Top 0.61: 5.84,25.65 4.83,25.65
  Top 0.66: 4.83,25.65 4.06,26.42 4.06,27.81 4.95,28.7 C10.2
  Top 0.762: 12.29,25.02 12.42,24.89 13.34,24.89 | v1.29,21.21 1.4,21.21
  Top 1.016: 12.29,25.02 11.15,26.16 11.18,26.16 6.35,26.16 5.84,25.65 5.46,25.27 C2.1 2.92,23.5 BUT.2_1 2.67,21.72 2.16,21.21 1.4,21.21 | v21.08,27.56 23.24,27.56 23.75,27.05 C9.2 R12.2 v27.3,27.05 | RST.1_1 1.14,3.05 1.91,3.81 v1.91,4.45 | C5.2 v6.99,7.11 8.13,5.97 C7.1 9.14,5.59 v12.12,5.59 13.21,5.59 13.54,5.26 v16.76,5.26 16.51,5.51 C8.1 | CON1.2 29.08,9.4 v29.08,8.46
  Bottom 0.381: 23.5,27.81 23.11,27.43 21.21,27.43 v21.08,27.56
  Bottom 0.508: v10.64,16.52 8.65,16.52 7.49,15.37 0.89,15.37 | 27.94,23.39 27.94,23.37 27.43,22.86 VR1.2 | v17.04,20.32 16.76,20.04 AGND_E.1 16.76,18.11 R3.2
  Bottom 0.762: 23.5,27.81 24.64,28.96 R2.2
  Bottom 1.016: v1.29,21.21 0.89,20.8 0.89,15.37 v0.89,9.91 0.89,8.13 1.91,7.11 | v27.3,27.05 C17.2 27.3,25.27 27.43,25.15 27.43,24.64 27.94,24.13 27.94,23.39 29.08,22.25 v29.08,8.46 29.08,5.59 24.38,0.89 20.07,0.89 UEXT.2 20.07,3.56 18.36,5.26 v16.76,5.26 | 20.32,26.04 C16.2 | 20.32,26.04 21.11,26.04 FET5.2 21.4,27.24 v21.08,27.56 | 20.32,26.04 C15.2 | v1.91,4.45 1.91,7.11 | 1.91,7.11 v6.99,7.11 | v12.12,5.59 12.12,8.31 v12.45,8.64 12.45,9.02 13.51,10.08 SD/MMC.6 16.08,10.08 C11.1 C12.1
  other vias: 8.26,0.89
  pour Top (isolate 0.254, rank 2): -2.54,33.02 33.02,33.02 33.02,-2.54 -2.54,-2.54
  pour Bottom (isolate 0.254, rank 2): -5.08,35.56 35.56,35.56 35.56,-5.08 -5.08,-5.08
N$2
  Bottom 0.406: R1.2 3.17,24.69 2.44,25.43 2.44,26.47 2.77,26.8
  Bottom 0.508: 2.77,26.8 3.56,26.8 4.19,27.43 4.19,28.57 4.45,28.83 7.51,28.83 FET4.1 8.18,29.36 21.52,29.36 21.8,29.08
  Bottom 1.016: 21.8,29.08 FET5.3
N$5
  Bottom 1.016: R6.1 28.83,28.57 TXLED.C
N$6
  Top 0.508: UEXT_PWR_E.2 21.21,8.38 R9.2
N$7  (3 unrouted)
N$8  (via drill 0.6)
  Top 0.762: v5.21,26.8 5.84,27.43 v9.14,27.43
  Bottom 0.762: v9.14,27.43 9.14,26.8 9.65,26.29 10.03,26.29 11.43,24.89 17.91,24.89 18.54,24.26 C16.1 18.8,24 19.3,23.5 21.21,23.5 22.1,24.38 C15.1
  Bottom 1.016: FET2.1 5.21,25.04 v5.21,26.8 5.21,27.64 FET4.3 | VR1.5 23.5,23.81 23.5,24.64 | C15.1 23.5,24.64 | 23.5,26.14 FET5.1 | 23.5,24.64 23.5,26.14 | R2.1 24.51,27.18 23.5,26.16 23.5,26.14
N$18
  Bottom 0.254: L2.1 21.21,11.05 21.21,12.7 20.83,13.08 18.41,13.08 R4.2
  Bottom 0.762: PWR/CTRL.2 23.11,5.54 20.07,8.59 L2.1
N$19
  Top 0.254: 24.64,1.29 24.26,1.67 24.26,2.54 23.37,3.43 23.37,3.94 R8.2
  Top 0.508: 24.64,1.29 24.91,1.02 25.3,1.02 FET1.1
  Top 1.016: R8.2 C13.2 22.61,6.73 22.35,6.99 R9.1
N$23
  Bottom 0.254: R7.1 1.5,24.87 1.5,27.71 1.4,27.81
  Bottom 0.508: 1.4,27.81 RXLED.C
N$118  (1 unrouted)
  Top 0.406: USB.GND2 10.99,27.18 14.94,27.18 | 14.94,27.18 USB.GND3 | USB.GND1 18.99,27.18 14.94,27.18
  Top 1.016: USB.GND2 10.17,28.7 C10.1
RESET
  Top 0.203: 11.81,10.15 11.38,9.73 9.86,9.73 9.83,9.75
  Top 0.254: 5.21,4.7 5.21,10.29 6.35,11.43 8.15,11.43 9.83,9.75
  Top 0.508: 11.81,10.15 U1.13
  Top 0.762: RST.2_1 2.67,2.03 4.83,4.19 R5.2 5.21,4.7 | CON2.13 6.35,11.94 6.35,11.43
SD_VCC
  Bottom 0.508: SD/MMC.4 15.4,12.28 16.26,11.43 C11.2
  Bottom 1.016: C11.2 C12.2 19.56,11.43 L2.2
TXLED  (via drill 0.3)
  Top 0.203: 19.01,10.08 19.58,9.5 19.58,7.21 19.91,6.88 21.21,6.88 21.79,6.3 21.79,4.01 v22.81,3 | v26.29,5.38 v26.29,7.67
  Top 0.305: 29.21,20.83 29.46,21.08 29.46,23.37 v29.21,23.62
  Top 0.508: CON1.20 29.21,20.83 | 19.01,10.08 U1.22
  Top 0.66: v27.25,20.83 CON1.20
  Bottom 0.152: v26.29,7.67 26.29,9.12 25.86,9.55 25.86,12.04 27.25,13.44 v27.25,20.83
  Bottom 0.203: v22.81,3 23.09,2.72 24.94,2.72 26.29,4.06 v26.29,5.38
  Bottom 0.508: R6.2 28.83,25.02 29.21,24.64 v29.21,23.62
UCAP
  Top 0.254: 8.43,16.59 7.87,17.14 7.87,18.16 7.29,18.75 7.29,20.19 6.4,21.08 6.1,21.08 5.97,21.21
  Top 0.508: U1.6 8.43,16.59 | 5.97,21.21 C2.2
V+  (via drill 0.5)
  Top 0.762: R10.2 19.94,5.71 v20.7,5.71
  Top 1.016: FET1.3 20.42,1.91 UEXT.1 19.81,2.52 R10.2
  Bottom 0.762: R11.2 19.43,6.99 v20.7,5.71 21.34,5.71 21.97,5.08 PWR/CTRL.1
VBUS
  Top 0.381: USB.VBUS 16.29,24.77 16.64,24.77
  Top 1.016: 16.64,24.77 17.53,24.77 18.69,25.93 L1.1
VCC  (via drill 0.5, 0.6)
  Top 0.406: U1.14 12.61,10.02 11.81,9.22 8.81,9.22 C5.1 | v11.66,13.21 13.08,13.21 14.5,14.63 14.5,17.73 15.7,18.92 16.76,18.92 18.8,20.95 18.8,21.18 19.01,21.39 19.01,22.35
  Top 0.508: U1.34 19.01,22.35 19.3,22.35 | R5.1 6.99,5.46 5.97,6.48 5.97,10.03 6.48,10.54 v7.92,10.54 7.92,10.41 8.76,9.58 C5.1
  Top 0.66: 24.38,6.48 23.44,7.42 23.44,8.43 22.91,8.97 v22.91,9.53 22.91,9.83 23.75,10.67 CON1.3
  Top 0.762: C6.1 v19.81,22.35 19.3,22.35 | 24.38,6.48 C13.1
  Top 1.016: C13.1 R8.1 v24.38,3.81 25.15,3.07 FET1.2
  Bottom 0.203: 2.29,23.88 2.29,24.84 1.93,25.2 1.93,27.2 2.54,27.81 | 26.29,26.67 25.96,26.34 24.84,26.34 24.64,26.14 24.64,23.42 24.11,22.89
  Bottom 0.254: 7.24,24 6.48,24 6.22,23.75 4.83,23.75 4.7,23.62 2.54,23.62 2.29,23.88 | 21.21,22.23 21.87,22.89 24.11,22.89
  Bottom 0.508: v7.92,10.54 7.92,11.99 9.14,13.21 v11.66,13.21 | TXLED.A 26.29,28.07 26.29,26.67 | RXLED.A 3.17,28.45 2.54,27.81
  Bottom 0.66: v19.81,22.35 C6.1 21.08,22.35 21.21,22.23 21.34,22.1 21.34,21.21 22.33,20.22 23.47,20.22 23.93,19.76 23.93,14.12 23.16,13.36 23.16,9.78 v22.91,9.53
  Bottom 0.762: v19.81,22.35 18.72,22.35 17.2,23.88 10.79,23.88 10.54,23.62 | v24.38,3.81 24.26,3.94 PWR/CTRL.3
  Bottom 1.016: FET4.2 7.58,26.75 6.92,26.1 FET2.2 6.92,24.32 7.24,24 7.62,23.62 9.02,23.62 | L3.1 9.02,22.48 9.02,23.62 | 10.54,23.62 9.02,23.62
VDD  (via drill 0.4, 0.5)
  Top 0.254: 21.97,11.81 21.95,11.84 21.95,13.11 21.66,13.39
  Top 0.406: U1.24 19.89,13.39 19.28,13.99 19.28,16.38 18.92,16.74 18.92,18.54 v19.38,19
  Top 0.508: U1.24 21.66,13.39 | U1.44 11.01,22.35 10.67,22.35 | 21.97,11.81 C3.1
  Top 0.762: CON2.1 6.1,19.94 v6.1,20.27
  Top 1.016: C4.1 9.65,22.35 v10.41,22.35 10.67,22.35
  Bottom 0.406: C14.1 17.22,22.73 19.38,20.57 v19.38,19
  Bottom 0.711: v6.1,20.27 6.91,21.08 9.91,21.08 10.41,21.59 v10.41,22.35
  Bottom 0.762: v10.41,22.35 10.54,22.48 L3.2 12.29,22.73 C14.1
VIN  (via drill 0.5)
  Top 0.762: D1.C 28.47,24.66 v26.16,24.66 | FET3.2 24.37,22.55 v25.15,21.77
  Bottom 0.559: 25.15,22.99 25.15,23.09 25.22,23.16 25.22,23.47 25.32,23.57
  Bottom 0.711: v25.15,21.77 25.15,22.99
  Bottom 0.762: 25.32,23.57 25.56,23.81 VR1.1 26.16,23.81 v26.16,24.66 25.53,25.3 C17.1 | VR1.3 25.29,21.91 v25.15,21.77
XTAL1
  Top 0.508: U1.17 15.01,8.53 14.68,8.2 Q1.2
  Top 1.016: Q1.2 15.08,8 C8.2
XTAL2
  Top 0.254: 14.21,9.71 13.34,8.84 13.34,8.23 12.72,7.62 11.56,7.62
  Top 0.508: 14.21,9.71 U1.16
  Top 1.016: 11.56,7.62 10.7,7.62 Q1.1 10.52,7.75 C7.2

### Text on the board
Top: 91 errors | 122 total
Bottom: 77 errors
tNames: (C) 2013 | Rev.B | OLIMEXINO-NANO
bNames: A | A | RoHS Compliant | https://www.olimex.com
